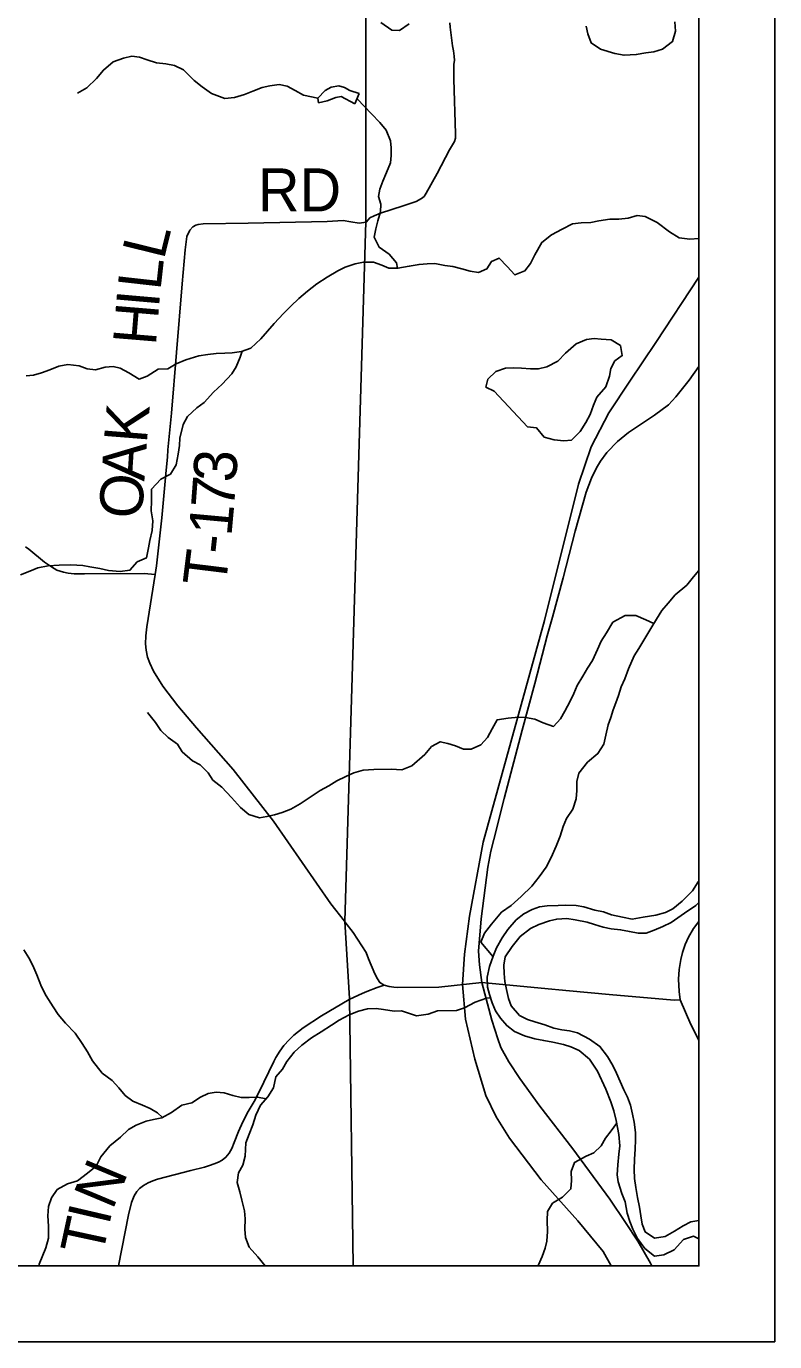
# Model space of a CAD drawing. Extents: x 0 to 34, y 0 to 22.
# Drawn here: x 8.013 to 9, y 14 to 15.737 of the extents above; entities that cross this region are included whole.
import ezdxf

# ---------------------------------------------------------------- set-up
doc = ezdxf.new("R2010")
doc.units = 0
for name, color, linetype in [('Default', 7, 'Continuous'), ('GM_X_County_Road', 7, 'Continuous'), ('GM_X_County_Road_Text', 7, 'Continuous'), ('GM_X_Major_River', 7, 'Continuous'), ('GM_X_Minor_Lake', 7, 'Continuous'), ('GM_X_Minor_River', 7, 'Continuous'), ('GM_X_Rail_Line', 7, 'Continuous'), ('GM_X_Township_Road', 7, 'Continuous'), ('GM_X_Township_Road_Text', 7, 'Continuous'), ('SH_Cut_Line', 7, 'Continuous'), ('SH_Data', 7, 'Continuous')]:
    doc.layers.add(name, color=color, linetype=linetype)

msp = doc.modelspace()

# ---------------------------------------------------------------- linework, layer by layer
at = {"layer": 'Default'}
msp.add_lwpolyline([(8.4439, 14.1), (8.9, 14.1), (8.9, 15.9304), (8.569, 15.9256), (8.4608, 15.9241), (8.4608, 15.4787), (8.4328, 14.5554), (8.4328, 14.555), (8.4391, 14.4529)], close=True, dxfattribs=at)
msp.add_lwpolyline([(3.2815, 15.7537), (3.2811, 15.7294), (3.2832, 14.8896), (3.2841, 14.501), (3.2822, 14.2781), (3.2808, 14.1155), (3.2807, 14.1), (8.4439, 14.1), (8.4391, 14.4529), (8.4328, 14.555), (8.4328, 14.5554), (8.4608, 15.4787), (8.4608, 15.9241)], dxfattribs=at)
at = {"layer": 'GM_X_County_Road'}
for points in [[(8.838, 14.1), (8.8362, 14.1036), (8.8195, 14.1326), (8.8034, 14.1575), (8.7826, 14.1883), (8.7336, 14.2548), (8.6903, 14.3109), (8.6636, 14.3474), (8.6493, 14.3696), (8.6388, 14.3886), (8.6346, 14.3997), (8.6267, 14.4243), (8.6135, 14.4744), (8.6105, 14.4976), (8.6094, 14.5158), (8.6129, 14.5581), (8.6214, 14.6266), (8.6255, 14.6475), (8.6293, 14.6632), (8.6429, 14.7174), (8.6667, 14.8075), (8.6836, 14.869), (8.7, 14.932), (8.707, 14.9566), (8.7209, 15.0086), (8.737, 15.0701), (8.7513, 15.1217), (8.7583, 15.1403), (8.7648, 15.1537), (8.7701, 15.1626), (8.7784, 15.1739), (8.7927, 15.1886), (8.8072, 15.2004), (8.8414, 15.2233), (8.8598, 15.2371), (8.8695, 15.2474), (8.8873, 15.2697), (8.9, 15.2874)], [(8.0118, 15.0495), (8.016, 15.0465), (8.0366, 15.0294), (8.0458, 15.0229), (8.0528, 15.0188), (8.0618, 15.0159), (8.068, 15.0149), (8.0757, 15.014), (8.0827, 15.0137), (8.0893, 15.0139), (8.1683, 15.0144), (8.1828, 15.0129), (8.1718, 14.944), (8.1704, 14.9319), (8.1697, 14.9215), (8.1709, 14.9131), (8.1727, 14.904), (8.1756, 14.896), (8.1804, 14.8851), (8.1927, 14.8656), (8.2126, 14.8395), (8.2374, 14.8104), (8.2854, 14.7554), (8.3389, 14.6874), (8.4144, 14.5783), (8.4324, 14.5552)], [(8.4324, 14.5552), (8.433, 14.5544), (8.4437, 14.5402), (8.4612, 14.5137), (8.4642, 14.5055), (8.4725, 14.4858), (8.4761, 14.4789), (8.479, 14.4742), (8.4849, 14.4706), (8.4912, 14.4691), (8.4977, 14.4683), (8.5027, 14.4677), (8.5568, 14.4682), (8.6135, 14.4744), (8.6229, 14.4735)], [(8.8754, 14.4513), (8.8741, 14.4624), (8.8731, 14.4786), (8.8739, 14.4916), (8.876, 14.5045), (8.8784, 14.5138), (8.8818, 14.5243), (8.8863, 14.5343), (8.8927, 14.5456), (8.9, 14.555)], [(8.4385, 14.4518), (8.4393, 14.4523), (8.4559, 14.4598), (8.4618, 14.4623), (8.4754, 14.4678), (8.4849, 14.4706)], [(8.6229, 14.4735), (8.692, 14.4666), (8.7291, 14.4633), (8.7816, 14.4582), (8.8672, 14.4508), (8.8754, 14.4513)], [(8.1342, 14.1), (8.1475, 14.1675), (8.1515, 14.1838), (8.155, 14.1927), (8.1585, 14.1985), (8.162, 14.2023), (8.1674, 14.2063), (8.1735, 14.2098), (8.1794, 14.2125), (8.1856, 14.2145), (8.2296, 14.2262), (8.2476, 14.2304), (8.2542, 14.2325), (8.2607, 14.2348), (8.2661, 14.2369), (8.2709, 14.2395), (8.2761, 14.2435), (8.2803, 14.2491), (8.2839, 14.2551), (8.2871, 14.2628), (8.2928, 14.2777), (8.2984, 14.2903), (8.3054, 14.304), (8.3132, 14.3171), (8.32, 14.3297), (8.326, 14.3428), (8.3391, 14.3699), (8.3419, 14.3752), (8.3472, 14.3838), (8.3523, 14.3911), (8.3593, 14.3986), (8.3655, 14.4047), (8.3779, 14.4146), (8.402, 14.4302), (8.4385, 14.4518)], [(8.9, 14.398), (8.8894, 14.419), (8.8754, 14.4513)]]:
    msp.add_lwpolyline(points, dxfattribs=at)
at = {"layer": 'GM_X_Major_River'}
for points in [[(8.9, 14.6078), (8.8992, 14.6073), (8.8914, 14.5954), (8.878, 14.5816), (8.8656, 14.5715), (8.8558, 14.5668), (8.8433, 14.5632), (8.8267, 14.5604), (8.8119, 14.5579), (8.7994, 14.5604), (8.7846, 14.5636), (8.7743, 14.5676), (8.7629, 14.5697), (8.7484, 14.5741), (8.7382, 14.5759), (8.7245, 14.5764), (8.7143, 14.5759), (8.6999, 14.5753), (8.6897, 14.5741), (8.6799, 14.5705), (8.669, 14.5647), (8.6588, 14.5569), (8.648, 14.5443), (8.6406, 14.5331), (8.6331, 14.5201), (8.6287, 14.5091), (8.6236, 14.4953), (8.6207, 14.4812), (8.6213, 14.4683), (8.6237, 14.4585), (8.6272, 14.4475), (8.6319, 14.4369), (8.6381, 14.4272), (8.6466, 14.4174), (8.6569, 14.4096), (8.6699, 14.404), (8.6836, 14.3997), (8.6954, 14.3975), (8.7075, 14.3954), (8.7212, 14.3922), (8.7311, 14.3893), (8.7422, 14.3845), (8.7556, 14.3729), (8.7664, 14.3571), (8.7773, 14.3333), (8.784, 14.3167), (8.7879, 14.305), (8.7907, 14.2921), (8.7944, 14.2736), (8.7957, 14.2588), (8.7943, 14.2477), (8.793, 14.2333), (8.7924, 14.2204), (8.7933, 14.2109), (8.7984, 14.1958), (8.8027, 14.1848), (8.8056, 14.1696), (8.8087, 14.1587), (8.813, 14.1485)], [(8.9, 14.16), (8.8895, 14.1582), (8.8793, 14.1528), (8.8677, 14.1458), (8.8556, 14.1388), (8.8416, 14.1367), (8.829, 14.1449), (8.8251, 14.1551), (8.8234, 14.1661), (8.8218, 14.1775), (8.8189, 14.1903), (8.8169, 14.2036), (8.8152, 14.2153), (8.8147, 14.2275), (8.8149, 14.2412), (8.8158, 14.2541), (8.8165, 14.2663), (8.8163, 14.2761), (8.8146, 14.2898), (8.8126, 14.3004), (8.8098, 14.3125), (8.8059, 14.3227), (8.8008, 14.3325), (8.7914, 14.3544), (8.7864, 14.3646), (8.7794, 14.3767), (8.7694, 14.3898), (8.7556, 14.3995), (8.74, 14.4076), (8.7293, 14.4105), (8.7194, 14.4119), (8.7088, 14.4141), (8.6966, 14.4185), (8.6837, 14.4225), (8.6738, 14.4254), (8.6635, 14.4305), (8.6523, 14.4433), (8.6488, 14.4531), (8.646, 14.4652), (8.6439, 14.4755), (8.6431, 14.4861), (8.6425, 14.4971), (8.6443, 14.5081), (8.6536, 14.5219), (8.6644, 14.535), (8.6779, 14.5454), (8.6888, 14.5509), (8.7028, 14.5556), (8.7126, 14.558), (8.7259, 14.5586), (8.7369, 14.5569), (8.7525, 14.5537), (8.7624, 14.5507), (8.7738, 14.5475), (8.7841, 14.5453), (8.7966, 14.544), (8.8084, 14.5415), (8.8201, 14.5394), (8.8304, 14.5395), (8.8409, 14.5435), (8.8526, 14.5482), (8.8636, 14.5533), (8.8812, 14.566), (8.8959, 14.5757), (8.9, 14.5797)], [(8.813, 14.1485), (8.8189, 14.1364), (8.8285, 14.1232), (8.8415, 14.1128), (8.8537, 14.1145), (8.8672, 14.1211), (8.8799, 14.1349), (8.8928, 14.1393), (8.9, 14.1359)]]:
    msp.add_lwpolyline(points, dxfattribs=at)
at = {"layer": 'GM_X_Minor_Lake'}
for points in [[(8.452, 15.648), (8.4395, 15.6521), (8.4326, 15.6558), (8.425, 15.658), (8.4148, 15.6564), (8.4069, 15.6521), (8.3971, 15.6418), (8.3983, 15.6357), (8.4096, 15.6381), (8.421, 15.6428), (8.4282, 15.644), (8.4461, 15.6343)], [(8.4461, 15.6343), (8.452, 15.648)], [(8.6741, 15.2078), (8.6859, 15.2064), (8.6959, 15.1943), (8.7092, 15.1906), (8.7217, 15.1892), (8.7319, 15.1901), (8.7432, 15.2016), (8.751, 15.2134), (8.7566, 15.2241), (8.7611, 15.2367), (8.7655, 15.247), (8.7772, 15.2608), (8.782, 15.2749), (8.7838, 15.2851), (8.789, 15.295), (8.7988, 15.302), (8.7968, 15.3152), (8.7842, 15.3227), (8.7713, 15.3237), (8.7618, 15.3244), (8.7516, 15.3232), (8.738, 15.3173), (8.7241, 15.3051), (8.7139, 15.2947), (8.6996, 15.287), (8.6883, 15.2846), (8.678, 15.2845), (8.6659, 15.2855), (8.6549, 15.2858), (8.645, 15.2853), (8.6322, 15.281), (8.6217, 15.271), (8.6191, 15.2604), (8.6301, 15.2552)], [(8.6301, 15.2552), (8.6741, 15.2078)]]:
    msp.add_lwpolyline(points, dxfattribs=at)
at = {"layer": 'GM_X_Minor_River'}
for points in [[(8.5179, 15.7401), (8.5051, 15.7313), (8.4949, 15.7316), (8.4804, 15.7417)], [(8.8682, 15.7427), (8.869, 15.7302), (8.865, 15.7165), (8.8518, 15.7065), (8.8404, 15.703), (8.8302, 15.7017), (8.8174, 15.6993), (8.8014, 15.6984), (8.7893, 15.7006), (8.7703, 15.7065), (8.7577, 15.7147), (8.7534, 15.7268), (8.7515, 15.7371)], [(8.3971, 15.6418), (8.3785, 15.6458), (8.3674, 15.6521), (8.3568, 15.6577), (8.3461, 15.6599), (8.334, 15.6583), (8.3238, 15.6559), (8.3117, 15.6512), (8.3004, 15.6466), (8.2872, 15.6426), (8.2747, 15.6414), (8.2572, 15.6481), (8.2446, 15.6567), (8.2343, 15.6653), (8.2201, 15.6792), (8.208, 15.6848), (8.1966, 15.6873), (8.1844, 15.6884), (8.1719, 15.6924), (8.162, 15.6958), (8.1518, 15.6972), (8.1408, 15.6948), (8.1272, 15.6897), (8.1144, 15.679), (8.1054, 15.6679), (8.0926, 15.6556), (8.0802, 15.6486)], [(8.5024, 15.4173), (8.5009, 15.4244), (8.4914, 15.4357), (8.4784, 15.4451), (8.4718, 15.4583), (8.4736, 15.4694), (8.4766, 15.48), (8.4799, 15.4918), (8.4802, 15.5017), (8.4774, 15.5119), (8.4789, 15.5218), (8.483, 15.5321), (8.4878, 15.5435), (8.493, 15.5565), (8.494, 15.566), (8.4939, 15.5763), (8.4931, 15.5857), (8.4873, 15.5997), (8.4793, 15.6095), (8.4682, 15.6212), (8.449, 15.641)], [(8.9, 15.4567), (8.8881, 15.4558), (8.874, 15.4576), (8.8614, 15.4655), (8.845, 15.4778), (8.829, 15.4857), (8.8188, 15.4871), (8.8067, 15.4832), (8.7942, 15.4819), (8.7825, 15.4822), (8.7681, 15.4798), (8.7575, 15.4778), (8.7446, 15.4773), (8.7332, 15.476), (8.7196, 15.469), (8.7057, 15.4613), (8.6929, 15.4513), (8.6836, 15.4349), (8.678, 15.4235), (8.6705, 15.4139), (8.6572, 15.4085), (8.6469, 15.4194), (8.6366, 15.4307), (8.6264, 15.426), (8.6204, 15.4165), (8.6091, 15.4118), (8.5981, 15.4136), (8.5871, 15.4165), (8.5753, 15.4195), (8.565, 15.4209), (8.5517, 15.4234), (8.5415, 15.4233), (8.5309, 15.4224), (8.518, 15.42), (8.5029, 15.4172), (8.4911, 15.4175), (8.4816, 15.4212), (8.4706, 15.4253), (8.4577, 15.4255), (8.4467, 15.4232), (8.4335, 15.4185), (8.4237, 15.4138), (8.4094, 15.4053), (8.3958, 15.3965), (8.3838, 15.3869), (8.3721, 15.3773), (8.3616, 15.3673), (8.3518, 15.3577), (8.3398, 15.3443), (8.3308, 15.3344), (8.3221, 15.324), (8.309, 15.3117), (8.2965, 15.3074), (8.2844, 15.3054), (8.2745, 15.305), (8.2632, 15.3049), (8.2522, 15.3036), (8.2401, 15.3016), (8.2231, 15.2965), (8.2102, 15.2911), (8.1993, 15.2845), (8.1868, 15.284), (8.1721, 15.2748), (8.1615, 15.2709), (8.1478, 15.2791), (8.1367, 15.2854), (8.1272, 15.2876), (8.1166, 15.2868), (8.1038, 15.2832), (8.0928, 15.2846), (8.0825, 15.2883), (8.0673, 15.2901)], [(8.2973, 15.3077), (8.2947, 15.2998), (8.2895, 15.2873), (8.2839, 15.2777), (8.2711, 15.2643), (8.2598, 15.2536), (8.2474, 15.2402), (8.2376, 15.2332), (8.2252, 15.2217), (8.2196, 15.211), (8.2152, 15.1928), (8.2146, 15.1833), (8.2131, 15.1719), (8.2102, 15.1578), (8.2028, 15.1456), (8.1903, 15.1386), (8.1779, 15.1256), (8.178, 15.1104), (8.1774, 15.0971), (8.1798, 15.0838), (8.1788, 15.0709), (8.1755, 15.058), (8.174, 15.0481), (8.1711, 15.0348), (8.159, 15.0297), (8.1493, 15.0186), (8.1364, 15.017), (8.1212, 15.0184), (8.1095, 15.0209), (8.0965, 15.0231), (8.0871, 15.0249), (8.0715, 15.0259), (8.056, 15.0253), (8.0416, 15.0244), (8.028, 15.0216), (8.0174, 15.0174), (8.0049, 15.0123)], [(8.0673, 15.2901), (8.0556, 15.2881), (8.0435, 15.283), (8.0329, 15.2791), (8.0223, 15.276), (8.0125, 15.2751)], [(8.9, 15.0183), (8.893, 15.0097), (8.884, 14.999), (8.8686, 14.986), (8.8596, 14.9752), (8.851, 14.9653), (8.8439, 14.9538), (8.8368, 14.9416), (8.8286, 14.9283), (8.8207, 14.9153), (8.8147, 14.9057), (8.8073, 14.8882), (8.8021, 14.8752), (8.7976, 14.8645), (8.7939, 14.8531), (8.7906, 14.8436), (8.7869, 14.8341), (8.784, 14.8242), (8.7803, 14.8143), (8.7773, 14.8009), (8.7748, 14.7888), (8.7669, 14.7765), (8.753, 14.765), (8.7418, 14.7505), (8.7388, 14.7398), (8.7389, 14.7277), (8.7383, 14.7167), (8.7338, 14.7033)], [(8.8405, 14.9481), (8.8299, 14.9529), (8.8169, 14.9589), (8.8029, 14.9588), (8.7867, 14.9499), (8.7781, 14.9361), (8.771, 14.9247), (8.7661, 14.914), (8.7598, 14.8995), (8.7531, 14.8892), (8.7471, 14.8785), (8.7396, 14.8663), (8.7352, 14.8556), (8.73, 14.8457), (8.7232, 14.8323), (8.7173, 14.8224), (8.7083, 14.8124), (8.6946, 14.8172), (8.6835, 14.8221), (8.6714, 14.8242), (8.6619, 14.8245), (8.6483, 14.8233), (8.6339, 14.8212), (8.6272, 14.809), (8.6212, 14.7976), (8.6122, 14.788), (8.5997, 14.7822), (8.5895, 14.7821), (8.5788, 14.7865), (8.569, 14.7899), (8.5587, 14.792), (8.5474, 14.7859), (8.5384, 14.7751), (8.5215, 14.7605), (8.5082, 14.7551), (8.4942, 14.7557), (8.4711, 14.7555), (8.4571, 14.7546), (8.4446, 14.7511), (8.4344, 14.7464), (8.4223, 14.7406), (8.4118, 14.7337), (8.4004, 14.7279), (8.3846, 14.7171), (8.3741, 14.7102), (8.3616, 14.7032), (8.3503, 14.6986), (8.3401, 14.6958), (8.3302, 14.6934), (8.3204, 14.6918), (8.3063, 14.6962), (8.2953, 14.7052), (8.2834, 14.7184), (8.2708, 14.732), (8.2589, 14.7414), (8.2528, 14.7512), (8.2421, 14.7617), (8.2318, 14.7669), (8.2181, 14.7789), (8.2123, 14.7887), (8.1997, 14.7977), (8.1902, 14.8068), (8.1829, 14.8177), (8.1725, 14.8309)], [(8.7338, 14.7033), (8.7252, 14.6907), (8.7208, 14.68), (8.7171, 14.6675), (8.7119, 14.6541), (8.7052, 14.6393), (8.6985, 14.6267), (8.6891, 14.6137), (8.6794, 14.6014), (8.6655, 14.5876), (8.6523, 14.5761), (8.6395, 14.5669), (8.6264, 14.5512), (8.617, 14.5393), (8.6125, 14.5275), (8.6284, 14.5082)], [(8.1922, 14.2958), (8.1856, 14.3021), (8.1761, 14.3077), (8.1658, 14.3121), (8.1532, 14.3177), (8.1433, 14.3251), (8.1348, 14.3353), (8.126, 14.345), (8.1126, 14.3547), (8.1002, 14.3709), (8.0932, 14.3829), (8.0863, 14.3938), (8.077, 14.4074), (8.0643, 14.4205), (8.0547, 14.4318), (8.0481, 14.4423), (8.0389, 14.4566), (8.0326, 14.4687), (8.0264, 14.4842), (8.0213, 14.4966), (8.0158, 14.5068), (8.0093, 14.5174)], [(8.6251, 14.454), (8.6196, 14.4535), (8.6049, 14.4483), (8.5906, 14.4409), (8.5804, 14.4374), (8.555, 14.437), (8.5429, 14.4323), (8.5274, 14.4302), (8.5076, 14.4368), (8.4978, 14.4366), (8.4837, 14.4384), (8.4742, 14.4397), (8.4628, 14.4396), (8.4511, 14.4364), (8.4387, 14.4317), (8.4255, 14.4243), (8.4154, 14.4177), (8.4015, 14.4091), (8.389, 14.4014), (8.3763, 14.3917), (8.3662, 14.3821), (8.3565, 14.3698), (8.3505, 14.3598), (8.342, 14.3495), (8.3387, 14.335), (8.3313, 14.3235), (8.3216, 14.3123), (8.3153, 14.2993), (8.3117, 14.2864), (8.3065, 14.2742), (8.3025, 14.2627), (8.3012, 14.2448), (8.2983, 14.233), (8.2928, 14.2231), (8.2907, 14.2101), (8.2942, 14.198), (8.297, 14.1867), (8.3006, 14.1727), (8.3015, 14.1624), (8.3009, 14.1484), (8.3018, 14.1377), (8.3066, 14.1249), (8.3181, 14.1121), (8.328, 14.1)], [(8.329, 14.3208), (8.3177, 14.3229), (8.3067, 14.3224), (8.2961, 14.3226), (8.285, 14.3251), (8.2736, 14.3284), (8.263, 14.3294), (8.2528, 14.3277), (8.2426, 14.3227), (8.231, 14.3153), (8.2177, 14.3125), (8.2042, 14.3024), (8.1914, 14.2954), (8.1804, 14.2933), (8.1706, 14.2913), (8.1574, 14.2858), (8.1473, 14.28), (8.1368, 14.27), (8.1229, 14.2588), (8.111, 14.2442), (8.105, 14.2319), (8.0934, 14.2223), (8.0803, 14.2126), (8.0671, 14.2086), (8.0535, 14.2008), (8.0461, 14.1901), (8.0421, 14.1783), (8.0411, 14.1661), (8.042, 14.1525), (8.0418, 14.1369), (8.0386, 14.1239), (8.0298, 14.1025), (8.029, 14.1)], [(8.7915, 14.2881), (8.7841, 14.2784), (8.777, 14.2688), (8.7711, 14.2584), (8.7613, 14.2492), (8.7515, 14.2449), (8.7357, 14.2367), (8.7317, 14.2249), (8.7319, 14.2127), (8.7312, 14.2017), (8.72, 14.1909), (8.7068, 14.1827), (8.7002, 14.172), (8.6999, 14.1599), (8.7005, 14.1454), (8.6995, 14.1329), (8.6974, 14.1234), (8.6933, 14.1123), (8.6882, 14.1016), (8.687, 14.1)]]:
    msp.add_lwpolyline(points, dxfattribs=at)
at = {"layer": 'GM_X_Rail_Line'}
msp.add_lwpolyline([(8.7841, 14.1), (8.7739, 14.119), (8.7401, 14.1594), (8.6918, 14.2135), (8.6501, 14.2688), (8.6325, 14.297), (8.6191, 14.325), (8.6044, 14.3732), (8.5921, 14.4259), (8.5882, 14.4718), (8.5908, 14.5117), (8.5975, 14.5618), (8.6155, 14.6595), (8.6962, 14.952), (8.7411, 15.1323), (8.758, 15.1814), (8.781, 15.2265), (8.8091, 15.2681), (8.8433, 15.3193), (8.9, 15.4054)], dxfattribs=at)
at = {"layer": 'GM_X_Township_Road'}
msp.add_lwpolyline([(8.4439, 14.1), (8.9, 14.1), (8.9, 15.9304), (8.569, 15.9256), (8.4608, 15.9241), (8.4608, 15.4787), (8.4328, 14.5552), (8.4328, 14.555), (8.4391, 14.4529)], close=True, dxfattribs=at)
for points in [[(8.4638, 15.4813), (8.4659, 15.4837), (8.4716, 15.4865), (8.4801, 15.4898), (8.5098, 15.4998), (8.5269, 15.5054), (8.5341, 15.5093), (8.5376, 15.5122), (8.5402, 15.5165), (8.5548, 15.5423), (8.5711, 15.5737), (8.5775, 15.5847), (8.5787, 15.589), (8.5791, 15.5949), (8.5766, 15.6668), (8.5765, 15.6866), (8.5775, 15.6915), (8.5771, 15.6974), (8.5763, 15.7045), (8.5751, 15.7111), (8.5718, 15.7355), (8.5716, 15.7414)], [(8.1828, 15.0129), (8.1846, 15.0242), (8.1915, 15.0876), (8.197, 15.1506), (8.1988, 15.1677), (8.1993, 15.1777), (8.2041, 15.2261), (8.2108, 15.3061), (8.2183, 15.3967), (8.2221, 15.4414), (8.2246, 15.4592), (8.2283, 15.4674), (8.2324, 15.472), (8.2362, 15.4741), (8.2394, 15.4752), (8.246, 15.4759), (8.3055, 15.4769), (8.4098, 15.4792), (8.4306, 15.4801), (8.441, 15.4786), (8.4519, 15.477), (8.4611, 15.4782), (8.4638, 15.4813)]]:
    msp.add_lwpolyline(points, dxfattribs=at)
at = {"layer": 'SH_Cut_Line'}
msp.add_lwpolyline([(3.2807, 14.1), (8.9, 14.1), (8.9, 20.9), (3.2826, 20.9), (3.2843, 20.6124), (3.2845, 20.5998), (3.2888, 19.8918), (3.2901, 19.68), (3.2904, 19.1173), (3.2907, 18.4315), (3.2837, 17.3796), (3.2835, 17.0107), (3.2832, 16.3898), (3.2829, 15.8433), (3.2815, 15.7537), (3.2811, 15.7294), (3.2832, 14.8896), (3.2841, 14.501), (3.2822, 14.2781), (3.2808, 14.1155)], close=True, dxfattribs=at)
at = {"layer": 'SH_Data'}
for p, q in [((9, 21), (9, 14)), ((8.9, 20.9), (8.9, 14.1)), ((2.1, 14.1), (8.9, 14.1)), ((2, 14), (9, 14))]:
    msp.add_line(p, q, dxfattribs=at)

# ---------------------------------------------------------------- texts
at = {"layer": 'GM_X_County_Road_Text'}
for s, rotation, p in [('N', 67.2319, (8.1263, 14.1727)), ('I', 76.8498, (8.1217, 14.1523)), ('T', 77.8403, (8.1128, 14.111))]:
    msp.add_text(s, height=0.0568, rotation=rotation, dxfattribs=at).set_placement(p)
at = {"layer": 'GM_X_Township_Road_Text'}
for s, height, rotation, p in [('RD', 0.05682, 0, (8.3183, 15.4923)), ('L', 0.0568, 76.1872, (8.194, 15.4273)), ('L', 0.0568, 83.6186, (8.1896, 15.387)), ('I', 0.0568, 85.0211, (8.1876, 15.3641)), ('H', 0.0568, 85.2663, (8.1835, 15.3143)), ('K', 0.0568, 85.4381, (8.1716, 15.1852)), ('A', 0.0568, 86.2891, (8.1684, 15.1355)), ('3', 0.0568, 86.0613, (8.2891, 15.1336)), ('O', 0.0568, 86.2964, (8.1651, 15.0856)), ('7', 0.0568, 85.7255, (8.2865, 15.0984)), ('1', 0.0568, 84.7975, (8.2832, 15.0625)), ('-', 0.0568, 83.8492, (8.2806, 15.0383)), ('T', 0.0568, 82.9366, (8.2753, 14.9951))]:
    msp.add_text(s, height=height, rotation=rotation, dxfattribs=at).set_placement(p)

doc.saveas('drawing.dxf')
